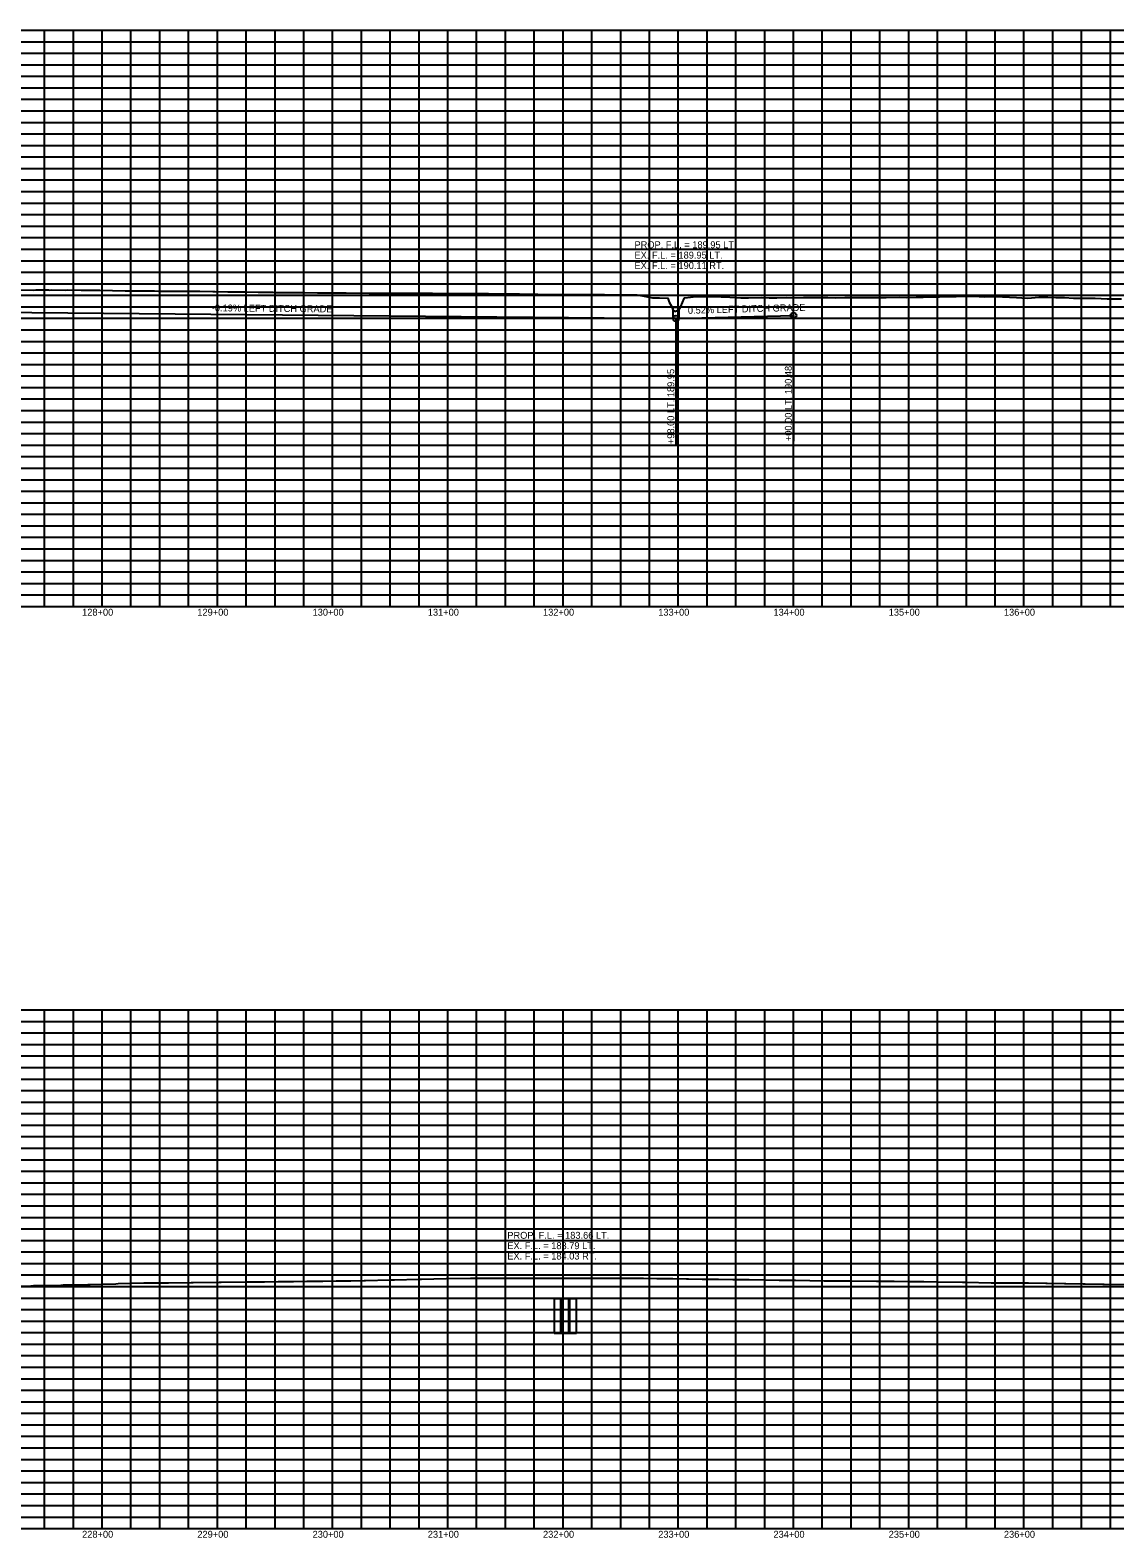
# Model space of a CAD drawing. Extents: x 1399671 to 1408349, y 1930471 to 1933387.
# Drawn here: x 1403062 to 1404003, y 1932071 to 1933379 of the extents above; entities that cross this region are included whole.
import ezdxf

# ---------------------------------------------------------------- set-up
doc = ezdxf.new("R2010")
doc.units = 0
for name, color, linetype in [('R_Drainage', 7, 'Continuous'), ('R_Exist Surface', 7, 'Continuous'), ('R_Grid', 7, 'Continuous'), ('R_Grid Annot', 7, 'Continuous'), ('R_Vert Alg', 7, 'Continuous'), ('R_Vert Alg Annot', 7, 'Continuous')]:
    doc.layers.add(name, color=color, linetype=linetype)

msp = doc.modelspace()

# ---------------------------------------------------------------- linework, layer by layer
at = {"layer": 'R_Drainage'}
for p, q in [((1403516.4, 1932278), (1403516.4, 1932248)), ((1403522.4, 1932278), (1403516.4, 1932278)), ((1403522.4, 1932248), (1403522.4, 1932278)), ((1403523.2, 1932278), (1403522.4, 1932278)), ((1403522.4, 1932278), (1403522.4, 1932248)), ((1403523.2, 1932278), (1403523.2, 1932248)), ((1403529.2, 1932278), (1403523.2, 1932278)), ((1403523.2, 1932248), (1403523.2, 1932278)), ((1403529.2, 1932248), (1403529.2, 1932278)), ((1403529.9, 1932278), (1403529.2, 1932278)), ((1403529.2, 1932278), (1403529.2, 1932248)), ((1403529.9, 1932278), (1403529.9, 1932248)), ((1403535.9, 1932278), (1403529.9, 1932278)), ((1403529.9, 1932248), (1403529.9, 1932278)), ((1403535.9, 1932248), (1403535.9, 1932278)), ((1403516.4, 1932248), (1403522.4, 1932248)), ((1403522.4, 1932248), (1403523.2, 1932248)), ((1403523.2, 1932248), (1403526.2, 1932248)), ((1403526.2, 1932248), (1403529.2, 1932248)), ((1403529.2, 1932248), (1403529.9, 1932248)), ((1403529.9, 1932248), (1403535.9, 1932248))]:
    msp.add_line(p, q, dxfattribs=at)
msp.add_lwpolyline([(1403619.7, 1933138.4), (1403624.7, 1933138.4), (1403624.7, 1933128.4), (1403619.7, 1933128.4)], close=True, dxfattribs=at)
at = {"layer": 'R_Exist Surface'}
for points in [[(1403053.5, 1933153.4), (1403064.5, 1933153.1), (1403066.9, 1933153.4), (1403077.9, 1933153.2), (1403078.3, 1933153.1), (1403080.5, 1933153.3), (1403092.1, 1933153.1), (1403094.1, 1933153.2), (1403106, 1933152.9), (1403107.8, 1933153), (1403109.6, 1933153), (1403120.5, 1933152.9), (1403122.3, 1933152.9), (1403133.2, 1933152.7), (1403144.1, 1933152.5), (1403146, 1933152.5), (1403156.8, 1933152.4), (1403158.7, 1933152.3), (1403169.6, 1933152.3), (1403173, 1933152.2), (1403183.9, 1933152.2), (1403194.8, 1933152.2), (1403198.2, 1933152.1), (1403209.1, 1933152.1), (1403220.3, 1933151.9), (1403222.2, 1933151.9), (1403233.4, 1933151.7), (1403235.3, 1933151.7), (1403246.6, 1933151.5), (1403248.5, 1933151.5), (1403259.7, 1933151.3), (1403261.6, 1933151.3), (1403272.5, 1933151.2), (1403274.4, 1933151.1), (1403285.3, 1933151.1), (1403287.3, 1933151), (1403298.2, 1933150.9), (1403300.2, 1933150.9), (1403311, 1933150.8), (1403313, 1933150.7), (1403332.7, 1933150.6), (1403336.1, 1933150.6), (1403355.8, 1933150.5), (1403359.1, 1933150.5), (1403370.3, 1933150.4), (1403373.8, 1933150.4), (1403385, 1933150.4), (1403396.1, 1933150.3), (1403399.6, 1933150.3), (1403410.8, 1933150.3), (1403413, 1933150.2), (1403433, 1933150.2), (1403435.2, 1933150.1), (1403455.3, 1933150.1), (1403457.4, 1933150), (1403459.6, 1933150), (1403471.1, 1933149.9), (1403475.1, 1933149.8), (1403486.4, 1933149.7), (1403497.7, 1933149.6), (1403502.2, 1933149.5), (1403513.1, 1933149.4), (1403532.4, 1933149.3), (1403535.2, 1933149.3), (1403537.8, 1933149.3), (1403557.6, 1933149.2), (1403560.1, 1933149.2), (1403571.4, 1933149.1), (1403573.8, 1933149.2), (1403585.3, 1933149.1), (1403588.2, 1933149.1), (1403594.7, 1933147.8), (1403601.7, 1933146.5), (1403608, 1933146.4), (1403615, 1933146.1), (1403616.3, 1933142.5), (1403618.2, 1933139), (1403619.6, 1933136), (1403621.2, 1933134.6), (1403624.6, 1933135.9), (1403626.4, 1933138.9), (1403629.3, 1933145.8), (1403629.3, 1933146.2), (1403629.5, 1933146.4), (1403629.9, 1933146.3), (1403639.8, 1933147.5), (1403652.9, 1933147.5), (1403661.5, 1933147.1), (1403668.8, 1933147), (1403678.5, 1933146.5), (1403685.1, 1933146.4), (1403696.3, 1933146.6), (1403703.1, 1933146.5), (1403709.8, 1933146.5), (1403718.4, 1933146.6), (1403724.6, 1933146.5), (1403733, 1933146.7), (1403739.3, 1933146.6), (1403747.6, 1933146.7), (1403754, 1933146.6), (1403760.3, 1933146.5), (1403768.7, 1933146.6), (1403781.1, 1933146.6), (1403792.4, 1933146.7), (1403804.5, 1933146.6), (1403816, 1933146.8), (1403822.2, 1933146.7), (1403830.5, 1933147), (1403836.6, 1933147), (1403844.9, 1933147.3), (1403851, 1933147.2), (1403859.4, 1933147.5), (1403865.5, 1933147.5), (1403874, 1933147.8), (1403880.8, 1933147.7), (1403889.8, 1933147.3), (1403899, 1933147.5), (1403905.5, 1933147.2), (1403911.6, 1933146.9), (1403917.8, 1933146.7), (1403922.3, 1933146.5), (1403927.6, 1933146.2), (1403937.2, 1933146.9), (1403945, 1933147), (1403951.9, 1933146.6), (1403959.3, 1933146.6), (1403967.2, 1933146.1), (1403974.1, 1933146.2), (1403986.1, 1933146.1), (1403996.4, 1933145.6), (1404008.9, 1933145.5)], [(1403040.5, 1932288.8), (1403062.3, 1932289.3), (1403064.6, 1932289.4), (1403066.9, 1932289.4), (1403088.2, 1932289.8), (1403090.3, 1932289.9), (1403111.7, 1932290.3), (1403113.8, 1932290.4), (1403136.1, 1932291), (1403138.2, 1932291.1), (1403160.5, 1932291.7), (1403180, 1932291.9), (1403181.9, 1932291.9), (1403201.4, 1932292.1), (1403203.3, 1932292.2), (1403225.6, 1932292.3), (1403227.5, 1932292.4), (1403250, 1932292.5), (1403251.7, 1932292.5), (1403252.6, 1932292.6), (1403264.2, 1932292.7), (1403265.1, 1932292.7), (1403276.8, 1932292.8), (1403277.7, 1932292.8), (1403289.3, 1932293), (1403290.3, 1932293), (1403301.9, 1932293.1), (1403302.9, 1932293.1), (1403314.6, 1932293.3), (1403315.6, 1932293.3), (1403327.3, 1932293.5), (1403339, 1932293.6), (1403340, 1932293.6), (1403351.7, 1932293.8), (1403352.7, 1932293.8), (1403373.9, 1932294.3), (1403375.9, 1932294.4), (1403377.9, 1932294.4), (1403399.1, 1932294.9), (1403401.3, 1932295), (1403422.6, 1932295.4), (1403443.9, 1932295.8), (1403446, 1932295.8), (1403467.8, 1932295.9), (1403470, 1932295.9), (1403472.1, 1932295.8), (1403493.9, 1932295.9), (1403495.1, 1932295.9), (1403506.8, 1932295.9), (1403518.6, 1932295.9), (1403519.8, 1932295.9), (1403531.5, 1932295.8), (1403532.7, 1932295.8), (1403544.5, 1932295.8), (1403545.6, 1932295.8), (1403567.8, 1932295.8), (1403569.8, 1932295.8), (1403592, 1932295.7), (1403594, 1932295.7), (1403605.7, 1932295.6), (1403607.7, 1932295.6), (1403619.5, 1932295.4), (1403631.3, 1932295.2), (1403633.1, 1932295.2), (1403645, 1932295), (1403645.9, 1932295), (1403658.3, 1932294.9), (1403659.2, 1932294.9), (1403671.6, 1932294.7), (1403672.5, 1932294.7), (1403685, 1932294.6), (1403685.8, 1932294.6), (1403698.3, 1932294.5), (1403699.2, 1932294.4), (1403711.7, 1932294.2), (1403712.6, 1932294.2), (1403725, 1932294), (1403726, 1932294), (1403738.4, 1932293.8), (1403750.9, 1932293.6), (1403751.8, 1932293.5), (1403773.3, 1932293.4), (1403774.9, 1932293.4), (1403796.3, 1932293.3), (1403797.9, 1932293.3), (1403810, 1932293.1), (1403811.6, 1932293.1), (1403823.7, 1932293), (1403835.7, 1932292.8), (1403837.4, 1932292.8), (1403849.5, 1932292.6), (1403870.9, 1932292.3), (1403872.5, 1932292.3), (1403874.1, 1932292.3), (1403895.6, 1932291.9), (1403896.8, 1932291.9), (1403911.8, 1932291.8), (1403926.8, 1932291.7), (1403928, 1932291.7), (1403943.1, 1932291.4), (1403944.2, 1932291.4), (1403959.4, 1932291.1), (1403960.4, 1932291.1), (1403975.7, 1932290.8), (1403976.5, 1932290.8), (1403977.4, 1932290.8), (1403992.7, 1932290.6), (1403993.9, 1932290.5), (1404016.3, 1932290.2)]]:
    msp.add_lwpolyline(points, dxfattribs=at)
at = {"layer": 'R_Grid'}
for p, q in [((1400324.2, 1933378.6), (1408224.2, 1933378.6)), ((1400324.2, 1933378.6), (1408224.2, 1933378.6)), ((1403074.2, 1932878.6), (1403074.2, 1933378.6)), ((1403099.2, 1932878.6), (1403099.2, 1933378.6)), ((1403124.2, 1932878.6), (1403124.2, 1933378.6)), ((1403149.2, 1932878.6), (1403149.2, 1933378.6)), ((1403174.2, 1932878.6), (1403174.2, 1933378.6)), ((1403199.2, 1932878.6), (1403199.2, 1933378.6)), ((1403224.2, 1932878.6), (1403224.2, 1933378.6)), ((1403249.2, 1932878.6), (1403249.2, 1933378.6)), ((1403274.2, 1932878.6), (1403274.2, 1933378.6)), ((1403299.2, 1932878.6), (1403299.2, 1933378.6)), ((1403324.2, 1932878.6), (1403324.2, 1933378.6)), ((1403349.2, 1932878.6), (1403349.2, 1933378.6)), ((1403374.2, 1932878.6), (1403374.2, 1933378.6)), ((1403399.2, 1932878.6), (1403399.2, 1933378.6)), ((1403424.2, 1932878.6), (1403424.2, 1933378.6)), ((1403449.2, 1932878.6), (1403449.2, 1933378.6)), ((1403474.2, 1932878.6), (1403474.2, 1933378.6)), ((1403499.2, 1932878.6), (1403499.2, 1933378.6)), ((1403524.2, 1932878.6), (1403524.2, 1933378.6)), ((1403549.2, 1932878.6), (1403549.2, 1933378.6)), ((1403574.2, 1932878.6), (1403574.2, 1933378.6)), ((1403599.2, 1932878.6), (1403599.2, 1933378.6)), ((1403624.2, 1932878.6), (1403624.2, 1933378.6)), ((1403649.2, 1932878.6), (1403649.2, 1933378.6)), ((1403674.2, 1932878.6), (1403674.2, 1933378.6)), ((1403699.2, 1932878.6), (1403699.2, 1933378.6)), ((1403724.2, 1932878.6), (1403724.2, 1933378.6)), ((1403749.2, 1932878.6), (1403749.2, 1933378.6)), ((1403774.2, 1932878.6), (1403774.2, 1933378.6)), ((1403799.2, 1932878.6), (1403799.2, 1933378.6)), ((1403824.2, 1932878.6), (1403824.2, 1933378.6)), ((1403849.2, 1932878.6), (1403849.2, 1933378.6)), ((1403874.2, 1932878.6), (1403874.2, 1933378.6)), ((1403899.2, 1932878.6), (1403899.2, 1933378.6)), ((1403924.2, 1932878.6), (1403924.2, 1933378.6)), ((1403949.2, 1932878.6), (1403949.2, 1933378.6)), ((1403974.2, 1932878.6), (1403974.2, 1933378.6)), ((1403999.2, 1932878.6), (1403999.2, 1933378.6)), ((1400324.2, 1933368.6), (1408224.2, 1933368.6)), ((1400324.2, 1933358.6), (1408224.2, 1933358.6)), ((1400324.2, 1933348.6), (1408224.2, 1933348.6)), ((1400324.2, 1933338.6), (1408224.2, 1933338.6)), ((1400324.2, 1933328.6), (1408224.2, 1933328.6)), ((1400324.2, 1933318.6), (1408224.2, 1933318.6)), ((1400324.2, 1933308.6), (1408224.2, 1933308.6)), ((1400324.2, 1933298.6), (1408224.2, 1933298.6)), ((1400324.2, 1933288.6), (1408224.2, 1933288.6)), ((1400324.2, 1933278.6), (1408224.2, 1933278.6)), ((1400324.2, 1933268.6), (1408224.2, 1933268.6)), ((1400324.2, 1933258.6), (1408224.2, 1933258.6)), ((1400324.2, 1933248.6), (1408224.2, 1933248.6)), ((1400324.2, 1933238.6), (1408224.2, 1933238.6)), ((1400324.2, 1933228.6), (1408224.2, 1933228.6)), ((1400324.2, 1933218.6), (1408224.2, 1933218.6)), ((1400324.2, 1933208.6), (1408224.2, 1933208.6)), ((1400324.2, 1933198.6), (1408224.2, 1933198.6)), ((1400324.2, 1933188.6), (1408224.2, 1933188.6)), ((1400324.2, 1933178.6), (1408224.2, 1933178.6)), ((1400324.2, 1933168.6), (1408224.2, 1933168.6)), ((1400324.2, 1933158.6), (1408224.2, 1933158.6)), ((1400324.2, 1933148.6), (1408224.2, 1933148.6)), ((1400324.2, 1933138.6), (1408224.2, 1933138.6)), ((1400324.2, 1933128.6), (1408224.2, 1933128.6)), ((1400324.2, 1933118.6), (1408224.2, 1933118.6)), ((1400324.2, 1933108.6), (1408224.2, 1933108.6)), ((1400324.2, 1933098.6), (1408224.2, 1933098.6)), ((1400324.2, 1933088.6), (1408224.2, 1933088.6)), ((1400324.2, 1933078.6), (1408224.2, 1933078.6)), ((1400324.2, 1933068.6), (1408224.2, 1933068.6)), ((1400324.2, 1933058.6), (1408224.2, 1933058.6)), ((1400324.2, 1933048.6), (1408224.2, 1933048.6)), ((1400324.2, 1933038.6), (1408224.2, 1933038.6)), ((1400324.2, 1933028.6), (1408224.2, 1933028.6)), ((1400324.2, 1933018.6), (1408224.2, 1933018.6)), ((1400324.2, 1933008.6), (1408224.2, 1933008.6)), ((1400324.2, 1932998.6), (1408224.2, 1932998.6)), ((1400324.2, 1932988.6), (1408224.2, 1932988.6)), ((1400324.2, 1932978.6), (1408224.2, 1932978.6)), ((1400324.2, 1932968.6), (1408224.2, 1932968.6)), ((1400324.2, 1932958.6), (1408224.2, 1932958.6)), ((1400324.2, 1932948.6), (1408224.2, 1932948.6)), ((1400324.2, 1932938.6), (1408224.2, 1932938.6)), ((1400324.2, 1932928.6), (1408224.2, 1932928.6)), ((1400324.2, 1932918.6), (1408224.2, 1932918.6)), ((1400324.2, 1932908.6), (1408224.2, 1932908.6)), ((1400324.2, 1932898.6), (1408224.2, 1932898.6)), ((1400324.2, 1932888.6), (1408224.2, 1932888.6)), ((1400324.2, 1932878.6), (1408224.2, 1932878.6)), ((1400324.2, 1932528.6), (1407124.2, 1932528.6)), ((1400324.2, 1932528.6), (1407124.2, 1932528.6)), ((1403074.2, 1932078.6), (1403074.2, 1932528.6)), ((1403099.2, 1932078.6), (1403099.2, 1932528.6)), ((1403124.2, 1932078.6), (1403124.2, 1932528.6)), ((1403149.2, 1932078.6), (1403149.2, 1932528.6)), ((1403174.2, 1932078.6), (1403174.2, 1932528.6)), ((1403199.2, 1932078.6), (1403199.2, 1932528.6)), ((1403224.2, 1932078.6), (1403224.2, 1932528.6)), ((1403249.2, 1932078.6), (1403249.2, 1932528.6)), ((1403274.2, 1932078.6), (1403274.2, 1932528.6)), ((1403299.2, 1932078.6), (1403299.2, 1932528.6)), ((1403324.2, 1932078.6), (1403324.2, 1932528.6)), ((1403349.2, 1932078.6), (1403349.2, 1932528.6)), ((1403374.2, 1932078.6), (1403374.2, 1932528.6)), ((1403399.2, 1932078.6), (1403399.2, 1932528.6)), ((1403424.2, 1932078.6), (1403424.2, 1932528.6)), ((1403449.2, 1932078.6), (1403449.2, 1932528.6)), ((1403474.2, 1932078.6), (1403474.2, 1932528.6)), ((1403499.2, 1932078.6), (1403499.2, 1932528.6)), ((1403524.2, 1932078.6), (1403524.2, 1932528.6)), ((1403549.2, 1932078.6), (1403549.2, 1932528.6)), ((1403574.2, 1932078.6), (1403574.2, 1932528.6)), ((1403599.2, 1932078.6), (1403599.2, 1932528.6)), ((1403624.2, 1932078.6), (1403624.2, 1932528.6)), ((1403649.2, 1932078.6), (1403649.2, 1932528.6)), ((1403674.2, 1932078.6), (1403674.2, 1932528.6)), ((1403699.2, 1932078.6), (1403699.2, 1932528.6)), ((1403724.2, 1932078.6), (1403724.2, 1932528.6)), ((1403749.2, 1932078.6), (1403749.2, 1932528.6)), ((1403774.2, 1932078.6), (1403774.2, 1932528.6)), ((1403799.2, 1932078.6), (1403799.2, 1932528.6)), ((1403824.2, 1932078.6), (1403824.2, 1932528.6)), ((1403849.2, 1932078.6), (1403849.2, 1932528.6)), ((1403874.2, 1932078.6), (1403874.2, 1932528.6)), ((1403899.2, 1932078.6), (1403899.2, 1932528.6)), ((1403924.2, 1932078.6), (1403924.2, 1932528.6)), ((1403949.2, 1932078.6), (1403949.2, 1932528.6)), ((1403974.2, 1932078.6), (1403974.2, 1932528.6)), ((1403999.2, 1932078.6), (1403999.2, 1932528.6)), ((1400324.2, 1932518.6), (1407124.2, 1932518.6)), ((1400324.2, 1932508.6), (1407124.2, 1932508.6)), ((1400324.2, 1932498.6), (1407124.2, 1932498.6)), ((1400324.2, 1932488.6), (1407124.2, 1932488.6)), ((1400324.2, 1932478.6), (1407124.2, 1932478.6)), ((1400324.2, 1932468.6), (1407124.2, 1932468.6)), ((1400324.2, 1932458.6), (1407124.2, 1932458.6)), ((1400324.2, 1932448.6), (1407124.2, 1932448.6)), ((1400324.2, 1932438.6), (1407124.2, 1932438.6)), ((1400324.2, 1932428.6), (1407124.2, 1932428.6)), ((1400324.2, 1932418.6), (1407124.2, 1932418.6)), ((1400324.2, 1932408.6), (1407124.2, 1932408.6)), ((1400324.2, 1932398.6), (1407124.2, 1932398.6)), ((1400324.2, 1932388.6), (1407124.2, 1932388.6)), ((1400324.2, 1932378.6), (1407124.2, 1932378.6)), ((1400324.2, 1932368.6), (1407124.2, 1932368.6)), ((1400324.2, 1932358.6), (1407124.2, 1932358.6)), ((1400324.2, 1932348.6), (1407124.2, 1932348.6)), ((1400324.2, 1932338.6), (1407124.2, 1932338.6)), ((1400324.2, 1932328.6), (1407124.2, 1932328.6)), ((1400324.2, 1932318.6), (1407124.2, 1932318.6)), ((1400324.2, 1932308.6), (1407124.2, 1932308.6)), ((1400324.2, 1932298.6), (1407124.2, 1932298.6)), ((1400324.2, 1932288.6), (1407124.2, 1932288.6)), ((1400324.2, 1932278.6), (1407124.2, 1932278.6)), ((1400324.2, 1932268.6), (1407124.2, 1932268.6)), ((1400324.2, 1932258.6), (1407124.2, 1932258.6)), ((1400324.2, 1932248.6), (1407124.2, 1932248.6)), ((1400324.2, 1932238.6), (1407124.2, 1932238.6)), ((1400324.2, 1932228.6), (1407124.2, 1932228.6)), ((1400324.2, 1932218.6), (1407124.2, 1932218.6)), ((1400324.2, 1932208.6), (1407124.2, 1932208.6)), ((1400324.2, 1932198.6), (1407124.2, 1932198.6)), ((1400324.2, 1932188.6), (1407124.2, 1932188.6)), ((1400324.2, 1932178.6), (1407124.2, 1932178.6)), ((1400324.2, 1932168.6), (1407124.2, 1932168.6)), ((1400324.2, 1932158.6), (1407124.2, 1932158.6)), ((1400324.2, 1932148.6), (1407124.2, 1932148.6)), ((1400324.2, 1932138.6), (1407124.2, 1932138.6)), ((1400324.2, 1932128.6), (1407124.2, 1932128.6)), ((1400324.2, 1932118.6), (1407124.2, 1932118.6)), ((1400324.2, 1932108.6), (1407124.2, 1932108.6)), ((1400324.2, 1932098.6), (1407124.2, 1932098.6)), ((1400324.2, 1932088.6), (1407124.2, 1932088.6)), ((1400324.2, 1932078.6), (1407124.2, 1932078.6))]:
    msp.add_line(p, q, dxfattribs=at)
at = {"layer": 'R_Vert Alg'}
for p, q in [((1401224.2, 1933151.2), (1403622.2, 1933128.4)), ((1403622.2, 1933128.4), (1403724.2, 1933131))]:
    msp.add_line(p, q, dxfattribs=at)
at = {"layer": 'R_Vert Alg Annot'}
for p, q in [((1403622.2, 1933128.4), (1403622.2, 1933103.4)), ((1403622.2, 1933128.4), (1403622.2, 1933103.4)), ((1403724.2, 1933131), (1403724.2, 1933106)), ((1403622.2, 1933103.4), (1403622.2, 1933019.4)), ((1403622.2, 1933103.4), (1403622.2, 1933019.4)), ((1403724.2, 1933106), (1403724.2, 1933022))]:
    msp.add_line(p, q, dxfattribs=at)
for centre in [(1403622.2, 1933128.4), (1403622.2, 1933128.4), (1403724.2, 1933131)]:
    msp.add_circle(centre, 2.5, dxfattribs=at)

# ---------------------------------------------------------------- texts
at = {"layer": 'R_Grid Annot'}
for s, p in [('128+00', (1403106.8, 1932870.6)), ('129+00', (1403206.8, 1932870.6)), ('130+00', (1403306.8, 1932870.6)), ('131+00', (1403406.8, 1932870.6)), ('132+00', (1403506.8, 1932870.6)), ('133+00', (1403606.8, 1932870.6)), ('134+00', (1403706.8, 1932870.6)), ('135+00', (1403806.8, 1932870.6)), ('136+00', (1403906.8, 1932870.6)), ('228+00', (1403106.8, 1932070.6)), ('229+00', (1403206.8, 1932070.6)), ('230+00', (1403306.8, 1932070.6)), ('231+00', (1403406.8, 1932070.6)), ('232+00', (1403506.8, 1932070.6)), ('233+00', (1403606.8, 1932070.6)), ('234+00', (1403706.8, 1932070.6)), ('235+00', (1403806.8, 1932070.6)), ('236+00', (1403906.8, 1932070.6))]:
    msp.add_text(s, height=6, dxfattribs=at).set_placement(p)
at = {"layer": 'R_Vert Alg Annot'}
for s, p in [('PROP. F.L. = 189.95 LT.', (1403586.2, 1933189.4)), ('EX. F.L. = 189.95 LT.', (1403586.2, 1933180.4)), ('EX. F.L. = 190.11 RT.', (1403586.2, 1933171.4)), ('PROP. F.L. = 183.66 LT.', (1403475.8, 1932330)), ('EX. F.L. = 183.79 LT.', (1403475.8, 1932321)), ('EX. F.L. = 184.03 RT.', (1403475.8, 1932312))]:
    msp.add_text(s, height=6, dxfattribs=at).set_placement(p)
for s, rotation, p in [('-0.19% LEFT DITCH GRADE', 359.4553, (1403219.3, 1933134.7)), ('0.52% LEFT DITCH GRADE', 1.4882, (1403632.6, 1933132.5)), ('+98.00 LT. 189.95', 90, (1403620.7, 1933019.4)), ('+98.00 LT. 189.95', 90, (1403620.7, 1933019.4)), ('+00.00 LT. 190.48', 90, (1403722.7, 1933022))]:
    msp.add_text(s, height=6, rotation=rotation, dxfattribs=at).set_placement(p)

doc.saveas('drawing.dxf')
